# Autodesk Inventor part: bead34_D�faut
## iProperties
Created: 2011-01
Part Number: bead34_D�faut
Document SubType Name: Modeling
Designer: eric
Density: 1 g/cm^3
Mass: 0.0737663 g
Surface Area: 2.05598 cm^2
Volume: 0.0737663 cm^3
Author: eric
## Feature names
1. Base1
